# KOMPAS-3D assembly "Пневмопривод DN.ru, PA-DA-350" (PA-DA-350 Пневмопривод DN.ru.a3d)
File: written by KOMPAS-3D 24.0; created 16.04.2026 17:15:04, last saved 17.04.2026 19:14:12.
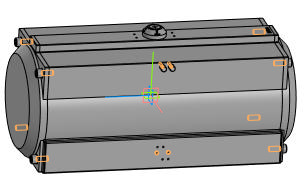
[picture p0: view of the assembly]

Document properties: Автор: DN.ru; Полное имя файла: C:\Работа\PA-DA-х Пневмопривод DN.ru\350\исходные материалы\PA-DA-350 Пневмопривод DN.ru.a3d

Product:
- Component [detail]: Пневмопривод DN.ru  | designation PA-DA-350  | qty 1  | pos. 1  | Масса: 186; Раздел спецификации: Прочие изделия; Примечание: D290-00303; Автор: DN.ru; source file: PA-DA-350 Пневмопривод DN.ru.m3d
- Component [standard]: Болт М10-6gx50 ГОСТ 7805-70  | qty 1  | pos. 2  | Масса: 0.04195; Раздел спецификации: Стандартные изделия; Рассекать на разрезах: no
- Component [standard]: Болт М10-6gx50 ГОСТ 7805-70  | qty 1  | Масса: 0.04195; Раздел спецификации: Стандартные изделия; Рассекать на разрезах: no
- Component [standard]: Гайка М10-6H ГОСТ 5915-70  | qty 1  | pos. 3  | Масса: 0.01206; Раздел спецификации: Стандартные изделия; Рассекать на разрезах: no
- Component [standard]: Гайка М10-6H ГОСТ 5915-70  | qty 1  | Масса: 0.01206; Раздел спецификации: Стандартные изделия; Рассекать на разрезах: no
- Component [standard]: Винт М20-6gx40 ГОСТ 11738-84  | qty 8  | pos. 4  | Масса: 0.17343; Раздел спецификации: Стандартные изделия; Рассекать на разрезах: no
- Part/product: Пневмопривод DN.ru  | designation PA-DA-350
    Масса: 186
    Раздел спецификации: Прочие изделия
    Примечание: D290-00303

Expressions: D290-00303
Referenced files in C:\Работа\PA-DA-х Пневмопривод DN.ru\350\исходные материалы\: PA-DA-350 Пневмопривод DN.ru.m3d
Referenced files in C:\Program Files\ASCON\KOMPAS-3D v24\Libs\PolynomLib\DATA\vault\Methods\Kompas\3D\: PLib_Screw_GOST_11738_1500.m3d, PLib_Bolt_1_900.m3d, PLib_Nut_OST92_900.m3d
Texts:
  PA-DA-350
  Крепежное изделие ГОСТ
  BOSimple***PART:f6352c65-8636-7196-6402-d592979e6031***SHORTLOC:Root±30±20±10±80±10±©{}30±©{BASE}130±30[Нет;Без покрытия;Без указания материала;50;10;17;1,5;-]
  BOSimple***PART:2c395b93-8c4a-cf39-bcf6-f45056cee6ca***SHORTLOC:Root±30±10±20±©{}110±10±50±60[Нет;Без покрытия;Без указания материала;-;10;1,5;17]
  BOSimple***PART:939ec6a4-9eca-958d-2272-ec7bb45f395d***SHORTLOC:Root±30±20±10±80±10±GMC90[Нет;Без покрытия;Без указания материала;2,5;-;40;20]
  Программные изделия  и базы данных
  PA-DA-350 Пневмопривод DN.ru
  Болт М10-6gx50 ГОСТ 7805-70 (1)
  hole1
  hole2
  Болт М10-6gx50 ГОСТ 7805-70 (2)
  Гайка М10-6H ГОСТ 5915-70 (1)
  bcut1
  hcut1
  cut1
  Гайка М10-6H ГОСТ 5915-70 (2)
  Винт М20-6gx40 ГОСТ 11738-84 (1)
  Винт М20-6gx40 ГОСТ 11738-84 (2)
  Винт М20-6gx40 ГОСТ 11738-84 (3)
  Винт М20-6gx40 ГОСТ 11738-84 (4)
  Винт М20-6gx40 ГОСТ 11738-84 (5)
  Винт М20-6gx40 ГОСТ 11738-84 (6)
  Винт М20-6gx40 ГОСТ 11738-84 (7)
  Винт М20-6gx40 ГОСТ 11738-84 (8)
  Plane. Начало координат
